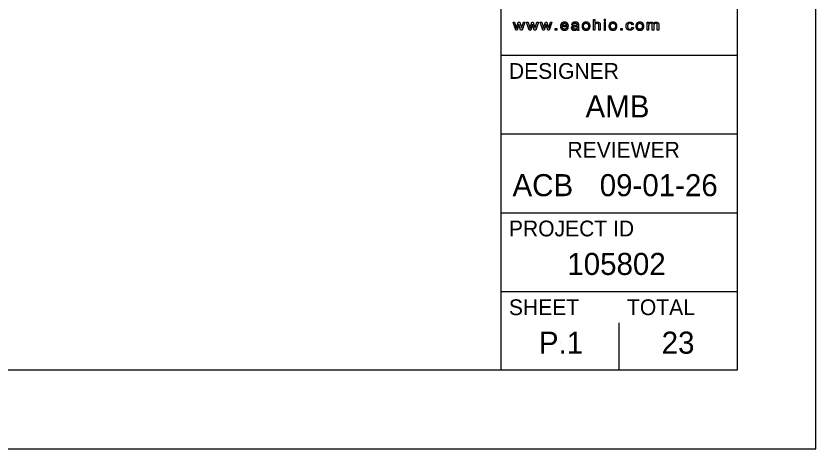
# Model space of a CAD drawing. Extents: x -8.3 to 34, y 0 to 22.
# Drawn here: x 28.92 to 34, y 0 to 2.75 of the extents above; entities that cross this region are included whole.
import ezdxf

# ---------------------------------------------------------------- set-up
doc = ezdxf.new("R2010")
doc.units = 0
for name, color, linetype in [('SH_Border', 7, 'Continuous'), ('SH_Cut_Line', 7, 'Continuous'), ('SH_Data', 7, 'Continuous'), ('TX_X_20', 7, 'Continuous')]:
    doc.layers.add(name, color=color, linetype=linetype)

msp = doc.modelspace()

# ---------------------------------------------------------------- linework, layer by layer
at = {"layer": 'SH_Border'}
for p, q in [((32, 0.5), (32, 21.5)), ((32, 2.5), (33.5, 2.5)), ((32, 2), (33.5, 2)), ((32, 1.5), (33.5, 1.5)), ((32, 1), (33.5, 1))]:
    msp.add_line(p, q, dxfattribs=at)
msp.add_lwpolyline([(1.5, 21.5), (33.5, 21.5), (33.5, 0.5), (1.5, 0.5)], close=True, dxfattribs=at)
at = {"layer": 'SH_Cut_Line'}
msp.add_lwpolyline([(0, 0), (34, 0), (34, 22), (0, 22)], close=True, dxfattribs=at)
at = {"layer": 'SH_Data'}
for p, q in [((32.75, 0.5), (32.75, 0.8)), ((32.375, 0.675), (32.375, 0.675))]:
    msp.add_line(p, q, dxfattribs=at)
at = {"layer": 'TX_X_20'}
for p, q in [((32.4477, 2.6948), (32.4567, 2.6937)), ((32.8402, 2.6944), (32.8313, 2.6931)), ((32.387, 2.6821), (32.4274, 2.6821)), ((32.4178, 2.6889), (32.3875, 2.6889)), ((32.4272, 2.6744), (32.4177, 2.6755)), ((32.4838, 2.6843), (32.4838, 2.6812)), ((32.4846, 2.6656), (32.4846, 2.6656)), ((32.4864, 2.6596), (32.496, 2.6596)), ((32.4931, 2.6802), (32.4931, 2.6913)), ((32.5143, 2.6842), (32.5143, 2.6842)), ((32.5238, 2.6842), (32.5238, 2.6842)), ((32.6852, 2.6842), (32.6852, 2.6842)), ((32.6946, 2.6842), (32.6946, 2.6842)), ((32.8321, 2.6776), (32.8411, 2.6765)), ((32.856, 2.6842), (32.856, 2.6842)), ((32.8655, 2.6842), (32.8655, 2.6842))]:
    msp.add_line(p, q, dxfattribs=at)
for points in [[(32.1007, 2.68), (32.1093, 2.7089), (32.1188, 2.7089), (32.1269, 2.6802), (32.1295, 2.6708), (32.1327, 2.6804), (32.142, 2.7089), (32.1509, 2.7089), (32.1339, 2.6596), (32.1244, 2.6596), (32.1158, 2.6891), (32.1137, 2.6975), (32.1027, 2.6596), (32.0931, 2.6596), (32.0766, 2.7089), (32.0861, 2.7089), (32.0947, 2.6804), (32.0979, 2.6698)], [(32.1867, 2.68), (32.1953, 2.7089), (32.2048, 2.7089), (32.2129, 2.6802), (32.2155, 2.6708), (32.2186, 2.6804), (32.228, 2.7089), (32.2369, 2.7089), (32.2199, 2.6596), (32.2104, 2.6596), (32.2018, 2.6891), (32.1997, 2.6975), (32.1886, 2.6596), (32.179, 2.6596), (32.1625, 2.7089), (32.172, 2.7089), (32.1807, 2.6804), (32.1838, 2.6698)], [(32.2726, 2.68), (32.2813, 2.7089), (32.2907, 2.7089), (32.2988, 2.6802), (32.3015, 2.6708), (32.3046, 2.6804), (32.3139, 2.7089), (32.3229, 2.7089), (32.3059, 2.6596), (32.2964, 2.6596), (32.2878, 2.6891), (32.2856, 2.6975), (32.2746, 2.6596), (32.265, 2.6596), (32.2485, 2.7089), (32.258, 2.7089), (32.2666, 2.6804), (32.2698, 2.6698)], [(32.5955, 2.6865), (32.5955, 2.6596), (32.5863, 2.6596), (32.5863, 2.7276), (32.5955, 2.7276), (32.5955, 2.7032)], [(32.9372, 2.6851), (32.9372, 2.6596), (32.928, 2.6596), (32.928, 2.7089), (32.9362, 2.7089), (32.9362, 2.7019)], [(33.0015, 2.6934), (33.0015, 2.6596), (32.9923, 2.6596), (32.9923, 2.6906)], [(32.6305, 2.6908), (32.6305, 2.6596), (32.6213, 2.6596), (32.6213, 2.6908)], [(32.9694, 2.6882), (32.9694, 2.6596), (32.9602, 2.6596), (32.9602, 2.6916)]]:
    msp.add_lwpolyline(points, dxfattribs=at)
for points in [[(32.655, 2.718), (32.6642, 2.718), (32.6642, 2.7276), (32.655, 2.7276)], [(32.655, 2.6596), (32.6642, 2.6596), (32.6642, 2.7089), (32.655, 2.7089)], [(32.3437, 2.6596), (32.3437, 2.669), (32.3541, 2.669), (32.3541, 2.6596)], [(32.7597, 2.6596), (32.7597, 2.669), (32.7702, 2.669), (32.7702, 2.6596)]]:
    msp.add_lwpolyline(points, close=True, dxfattribs=at)
for points in [[(32.3846, 2.7031), (32.3775, 2.6962), (32.3775, 2.6838)], [(32.4028, 2.71), (32.3916, 2.71), (32.3846, 2.7031)], [(32.3875, 2.6889), (32.388, 2.6954), (32.3923, 2.6992)], [(32.3923, 2.6992), (32.3966, 2.7031), (32.4029, 2.7031)], [(32.4206, 2.7032), (32.4137, 2.71), (32.4028, 2.71)], [(32.4029, 2.7031), (32.4099, 2.7031), (32.4143, 2.6983)], [(32.4143, 2.6983), (32.4172, 2.6951), (32.4178, 2.6889)], [(32.4275, 2.6843), (32.4275, 2.6965), (32.4206, 2.7032)], [(32.4517, 2.7032), (32.4489, 2.7), (32.4477, 2.6948)], [(32.4598, 2.7082), (32.4545, 2.7065), (32.4517, 2.7032)], [(32.4567, 2.6937), (32.4581, 2.6989), (32.4612, 2.701)], [(32.4721, 2.71), (32.4651, 2.71), (32.4598, 2.7082)], [(32.4612, 2.701), (32.4643, 2.7031), (32.4708, 2.7031)], [(32.4708, 2.7031), (32.4777, 2.7031), (32.4812, 2.7002)], [(32.4834, 2.7085), (32.479, 2.71), (32.4721, 2.71)], [(32.4812, 2.7002), (32.4838, 2.6981), (32.4838, 2.693)], [(32.4897, 2.7047), (32.4877, 2.707), (32.4834, 2.7085)], [(32.4838, 2.693), (32.4838, 2.6925), (32.4838, 2.6908)], [(32.4926, 2.699), (32.4918, 2.7025), (32.4897, 2.7047)], [(32.4931, 2.6913), (32.4931, 2.6969), (32.4926, 2.699)], [(32.5227, 2.7045), (32.5143, 2.6979), (32.5143, 2.6842)], [(32.5398, 2.71), (32.5297, 2.71), (32.5227, 2.7045)], [(32.5238, 2.6842), (32.5238, 2.6937), (32.5283, 2.6984)], [(32.5283, 2.6984), (32.5329, 2.7031), (32.5398, 2.7031)], [(32.558, 2.7033), (32.5509, 2.71), (32.5398, 2.71)], [(32.5398, 2.7031), (32.5465, 2.7031), (32.5511, 2.6983)], [(32.5511, 2.6983), (32.5556, 2.6936), (32.5556, 2.6845)], [(32.5651, 2.6849), (32.5651, 2.6966), (32.558, 2.7033)], [(32.5955, 2.7032), (32.602, 2.71), (32.6118, 2.71)], [(32.5971, 2.6956), (32.5955, 2.6923), (32.5955, 2.6865)], [(32.6022, 2.7008), (32.5986, 2.6989), (32.5971, 2.6956)], [(32.6099, 2.7028), (32.6058, 2.7028), (32.6022, 2.7008)], [(32.6183, 2.6999), (32.6153, 2.7028), (32.6099, 2.7028)], [(32.6118, 2.71), (32.6178, 2.71), (32.6222, 2.7078)], [(32.6213, 2.6908), (32.6213, 2.697), (32.6183, 2.6999)], [(32.6222, 2.7078), (32.6267, 2.7056), (32.6286, 2.7018)], [(32.6286, 2.7018), (32.6305, 2.698), (32.6305, 2.6908)], [(32.6935, 2.7045), (32.6852, 2.6979), (32.6852, 2.6842)], [(32.7106, 2.71), (32.7005, 2.71), (32.6935, 2.7045)], [(32.6946, 2.6842), (32.6946, 2.6937), (32.6992, 2.6984)], [(32.6992, 2.6984), (32.7037, 2.7031), (32.7106, 2.7031)], [(32.7288, 2.7033), (32.7218, 2.71), (32.7106, 2.71)], [(32.7106, 2.7031), (32.7174, 2.7031), (32.7219, 2.6983)], [(32.7219, 2.6983), (32.7265, 2.6936), (32.7265, 2.6845)], [(32.7359, 2.6849), (32.7359, 2.6966), (32.7288, 2.7033)], [(32.7939, 2.684), (32.7939, 2.692), (32.7968, 2.698)], [(32.7968, 2.698), (32.7997, 2.704), (32.8056, 2.707)], [(32.8077, 2.6986), (32.8033, 2.6941), (32.8033, 2.6843)], [(32.8056, 2.707), (32.8116, 2.71), (32.8186, 2.71)], [(32.8189, 2.7031), (32.812, 2.7031), (32.8077, 2.6986)], [(32.8186, 2.71), (32.8274, 2.71), (32.833, 2.7059)], [(32.8268, 2.7006), (32.8235, 2.7031), (32.8189, 2.7031)], [(32.8313, 2.6931), (32.83, 2.6981), (32.8268, 2.7006)], [(32.833, 2.7059), (32.8387, 2.7018), (32.8402, 2.6944)], [(32.8644, 2.7045), (32.856, 2.6979), (32.856, 2.6842)], [(32.8814, 2.71), (32.8714, 2.71), (32.8644, 2.7045)], [(32.8655, 2.6842), (32.8655, 2.6937), (32.87, 2.6984)], [(32.87, 2.6984), (32.8745, 2.7031), (32.8814, 2.7031)], [(32.8997, 2.7033), (32.8926, 2.71), (32.8814, 2.71)], [(32.8814, 2.7031), (32.8882, 2.7031), (32.8927, 2.6983)], [(32.8927, 2.6983), (32.8973, 2.6936), (32.8973, 2.6845)], [(32.9068, 2.6849), (32.9068, 2.6966), (32.8997, 2.7033)], [(32.9362, 2.7019), (32.9388, 2.7055), (32.943, 2.7077)], [(32.9387, 2.6954), (32.9372, 2.6918), (32.9372, 2.6851)], [(32.9434, 2.7008), (32.9401, 2.699), (32.9387, 2.6954)], [(32.943, 2.7077), (32.9472, 2.71), (32.9527, 2.71)], [(32.9506, 2.7027), (32.9467, 2.7027), (32.9434, 2.7008)], [(32.958, 2.6999), (32.9557, 2.7027), (32.9506, 2.7027)], [(32.9527, 2.71), (32.9587, 2.71), (32.9625, 2.7077)], [(32.9602, 2.6916), (32.9602, 2.6971), (32.958, 2.6999)], [(32.9625, 2.7077), (32.9664, 2.7054), (32.968, 2.7013)], [(32.968, 2.7013), (32.9744, 2.71), (32.9847, 2.71)], [(32.9732, 2.6992), (32.9694, 2.6958), (32.9694, 2.6882)], [(32.9827, 2.7027), (32.977, 2.7027), (32.9732, 2.6992)], [(32.9882, 2.7014), (32.9858, 2.7027), (32.9827, 2.7027)], [(32.9847, 2.71), (32.9928, 2.71), (32.9972, 2.7059)], [(32.9914, 2.6978), (32.9905, 2.7), (32.9882, 2.7014)], [(32.9923, 2.6906), (32.9923, 2.6956), (32.9914, 2.6978)], [(32.9972, 2.7059), (33.0015, 2.7018), (33.0015, 2.6934)], [(32.0979, 2.6698), (32.0981, 2.6706), (32.1007, 2.68)], [(32.1838, 2.6698), (32.184, 2.6706), (32.1867, 2.68)], [(32.2698, 2.6698), (32.27, 2.6706), (32.2726, 2.68)], [(32.3775, 2.6838), (32.3775, 2.6718), (32.3845, 2.6651)], [(32.3845, 2.6651), (32.3915, 2.6585), (32.4034, 2.6585)], [(32.3921, 2.6696), (32.3875, 2.6739), (32.387, 2.6821)], [(32.4034, 2.6653), (32.3966, 2.6653), (32.3921, 2.6696)], [(32.412, 2.6677), (32.4085, 2.6653), (32.4034, 2.6653)], [(32.4034, 2.6585), (32.4128, 2.6585), (32.4189, 2.6626)], [(32.4177, 2.6755), (32.4156, 2.6702), (32.412, 2.6677)], [(32.4189, 2.6626), (32.4249, 2.6668), (32.4272, 2.6744)], [(32.4274, 2.6821), (32.4275, 2.6835), (32.4275, 2.6843)], [(32.4479, 2.6792), (32.4461, 2.6762), (32.4461, 2.6726)], [(32.4461, 2.6726), (32.4461, 2.6664), (32.4509, 2.6624)], [(32.4526, 2.684), (32.4497, 2.6822), (32.4479, 2.6792)], [(32.4509, 2.6624), (32.4556, 2.6585), (32.4646, 2.6585)], [(32.4592, 2.6867), (32.4555, 2.6858), (32.4526, 2.684)], [(32.4559, 2.6728), (32.4559, 2.675), (32.4571, 2.6768)], [(32.4586, 2.6672), (32.4559, 2.6695), (32.4559, 2.6728)], [(32.4571, 2.6768), (32.4584, 2.6785), (32.4608, 2.6795)], [(32.4668, 2.665), (32.4614, 2.665), (32.4586, 2.6672)], [(32.4674, 2.688), (32.4619, 2.6873), (32.4592, 2.6867)], [(32.4608, 2.6795), (32.4631, 2.6804), (32.4688, 2.6811)], [(32.4646, 2.6585), (32.47, 2.6585), (32.4747, 2.6601)], [(32.4762, 2.6671), (32.4721, 2.665), (32.4668, 2.665)], [(32.4838, 2.6908), (32.4785, 2.6892), (32.4674, 2.688)], [(32.4688, 2.6811), (32.4788, 2.6824), (32.4838, 2.6843)], [(32.4747, 2.6601), (32.4794, 2.6617), (32.4846, 2.6656)], [(32.4823, 2.6729), (32.4803, 2.6692), (32.4762, 2.6671)], [(32.4838, 2.6812), (32.4838, 2.6757), (32.4823, 2.6729)], [(32.4846, 2.6656), (32.485, 2.6622), (32.4864, 2.6596)], [(32.4936, 2.6655), (32.4931, 2.6686), (32.4931, 2.6802)], [(32.496, 2.6596), (32.4942, 2.6624), (32.4936, 2.6655)], [(32.5143, 2.6842), (32.5143, 2.6717), (32.5214, 2.6651)], [(32.5214, 2.6651), (32.5284, 2.6585), (32.5398, 2.6585)], [(32.5283, 2.67), (32.5238, 2.6747), (32.5238, 2.6842)], [(32.5398, 2.6653), (32.5329, 2.6653), (32.5283, 2.67)], [(32.5511, 2.6701), (32.5466, 2.6653), (32.5398, 2.6653)], [(32.5398, 2.6585), (32.5468, 2.6585), (32.5528, 2.6615)], [(32.5556, 2.6845), (32.5556, 2.6748), (32.5511, 2.6701)], [(32.5528, 2.6615), (32.5588, 2.6645), (32.562, 2.67)], [(32.562, 2.67), (32.5651, 2.6754), (32.5651, 2.6849)], [(32.6852, 2.6842), (32.6852, 2.6717), (32.6922, 2.6651)], [(32.6922, 2.6651), (32.6992, 2.6585), (32.7106, 2.6585)], [(32.6992, 2.67), (32.6946, 2.6747), (32.6946, 2.6842)], [(32.7106, 2.6653), (32.7037, 2.6653), (32.6992, 2.67)], [(32.7219, 2.6701), (32.7174, 2.6653), (32.7106, 2.6653)], [(32.7106, 2.6585), (32.7177, 2.6585), (32.7237, 2.6615)], [(32.7265, 2.6845), (32.7265, 2.6748), (32.7219, 2.6701)], [(32.7237, 2.6615), (32.7297, 2.6645), (32.7328, 2.67)], [(32.7328, 2.67), (32.7359, 2.6754), (32.7359, 2.6849)], [(32.8006, 2.6651), (32.7939, 2.6717), (32.7939, 2.684)], [(32.8185, 2.6585), (32.8074, 2.6585), (32.8006, 2.6651)], [(32.8033, 2.6843), (32.8033, 2.6743), (32.8075, 2.6698)], [(32.8075, 2.6698), (32.8117, 2.6653), (32.8185, 2.6653)], [(32.8185, 2.6653), (32.8239, 2.6653), (32.8275, 2.6683)], [(32.8335, 2.6633), (32.8274, 2.6585), (32.8185, 2.6585)], [(32.8275, 2.6683), (32.8311, 2.6713), (32.8321, 2.6776)], [(32.8411, 2.6765), (32.8396, 2.668), (32.8335, 2.6633)], [(32.856, 2.6842), (32.856, 2.6717), (32.863, 2.6651)], [(32.863, 2.6651), (32.87, 2.6585), (32.8814, 2.6585)], [(32.87, 2.67), (32.8655, 2.6747), (32.8655, 2.6842)], [(32.8814, 2.6653), (32.8745, 2.6653), (32.87, 2.67)], [(32.8928, 2.6701), (32.8882, 2.6653), (32.8814, 2.6653)], [(32.8814, 2.6585), (32.8885, 2.6585), (32.8945, 2.6615)], [(32.8973, 2.6845), (32.8973, 2.6748), (32.8928, 2.6701)], [(32.8945, 2.6615), (32.9005, 2.6645), (32.9036, 2.67)], [(32.9036, 2.67), (32.9068, 2.6754), (32.9068, 2.6849)]]:
    msp.add_open_spline(points, degree=2, dxfattribs=at)

# ---------------------------------------------------------------- texts
at = {"layer": 'SH_Data'}
for s, height, p in [('DESIGNER', 0.1, (32.05, 2.35)), ('AMB', 0.14, (32.5366, 2.105)), ('REVIEWER', 0.1, (32.4218, 1.85)), ('ACB', 0.14, (32.0729, 1.605)), ('09-01-26', 0.14, (32.6266, 1.605)), ('PROJECT ID', 0.1, (32.05, 1.35)), ('105802', 0.14, (32.4209, 1.105)), ('SHEET', 0.1, (32.05, 0.85)), ('TOTAL', 0.1, (32.8, 0.85)), ('P.1', 0.14, (32.2403, 0.605)), ('23', 0.14, (33.02, 0.605))]:
    msp.add_text(s, height=height, dxfattribs=at).set_placement(p)

doc.saveas('drawing.dxf')
